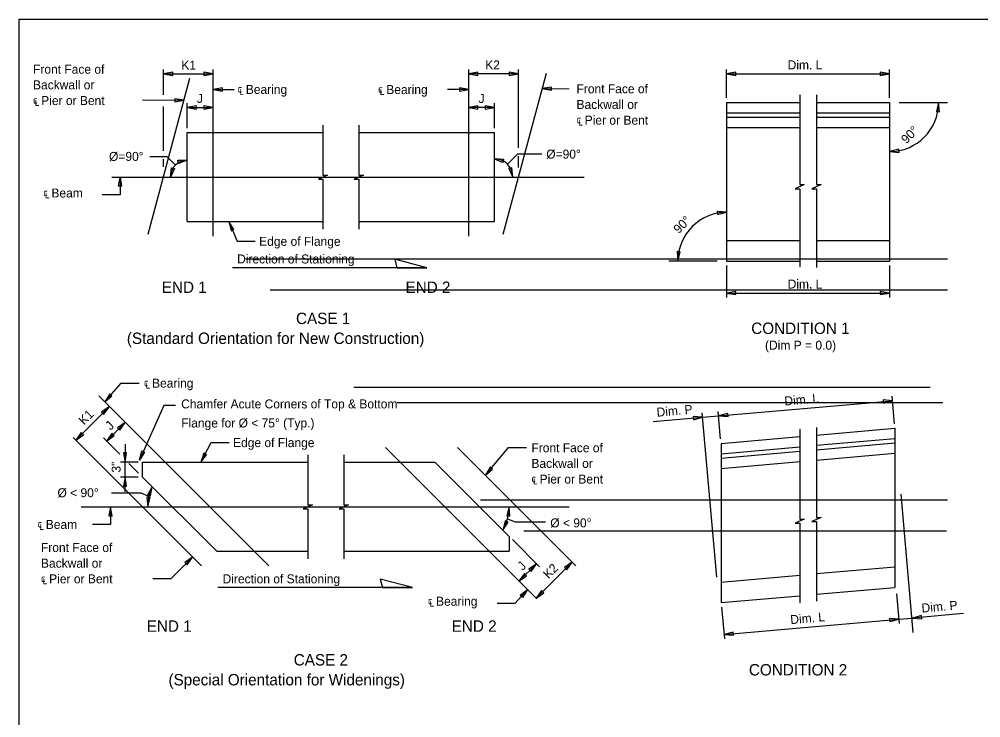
# Model space of a CAD drawing. Extents: x -119 to 80, y -12 to 144.
# Drawn here: x -12.03 to 4.16, y 47.86 to 59.63 of the extents above; entities that cross this region are included whole.
import ezdxf

# ---------------------------------------------------------------- set-up
doc = ezdxf.new("R2010")
doc.units = 0
for name, color, linetype in [('ActivePts-ConstElements', 7, 'Continuous'), ('AdhocPoint_dp', 7, 'Continuous'), ('CL_Major', 7, 'Continuous'), ('Patterning', 7, 'Continuous'), ('SheetLines_dp', 7, 'Continuous'), ('TextMisc', 7, 'Continuous')]:
    doc.layers.add(name, color=color, linetype=linetype)

msp = doc.modelspace()

# ---------------------------------------------------------------- linework, layer by layer
at = {"layer": 'ActivePts-ConstElements'}
msp.add_lwpolyline([(-12.032, 59.628), (18.768, 59.628), (18.768, 39.828), (-12.032, 39.828)], close=True, dxfattribs=at)
at = {"layer": 'AdhocPoint_dp'}
for p, q in [((-9.604, 58.355), (-9.604, 58.783)), ((-3.626, 57.46), (-3.626, 58.783)), ((-0.122, 58.302), (-0.122, 58.783)), ((2.623, 58.302), (2.623, 58.783)), ((-9.604, 58.707), (-8.766, 58.707)), ((-3.626, 58.707), (-4.464, 58.707)), ((-0.122, 58.707), (2.623, 58.707)), ((-3.227, 58.46), (-2.772, 58.457)), ((-8.766, 58.444), (-8.411, 58.444)), ((-4.464, 58.444), (-4.82, 58.444)), ((-9.258, 58.263), (-9.954, 58.259)), ((-9.604, 57.412), (-9.604, 58.157)), ((-9.202, 57.796), (-9.202, 58.217)), ((-9.202, 58.141), (-8.766, 58.141)), ((-4.029, 58.141), (-4.464, 58.141)), ((-4.029, 57.796), (-4.029, 58.217)), ((2.786, 58.226), (3.599, 58.226)), ((-3.626, 57.132), (-3.626, 57.322)), ((-9.604, 57.14), (-9.604, 57.27)), ((-10.334, 56.97), (-10.334, 56.669)), ((-10.334, 56.669), (-10.637, 56.669)), ((-8.501, 56.22), (-8.362, 55.888)), ((-8.362, 55.888), (-8.06, 55.888)), ((-0.28, 55.556), (-1.093, 55.556)), ((-5.167, 55.444), (-8.442, 55.444)), ((-0.122, 55.481), (-0.122, 54.942)), ((2.623, 55.481), (2.623, 54.942)), ((-0.122, 55.017), (2.623, 55.017)), ((-10.592, 53.183), (-10.315, 53.5)), ((-10.315, 53.5), (-10.012, 53.5)), ((2.706, 52.816), (2.665, 53.279)), ((-11.081, 52.538), (-10.514, 53.105)), ((-0.256, 52.948), (2.672, 53.204)), ((-0.289, 50.233), (-0.531, 53)), ((-0.525, 52.924), (-0.256, 52.948)), ((-0.222, 52.56), (-0.263, 53.023)), ((-10.561, 52.524), (-10.247, 52.838)), ((-1.356, 52.852), (-0.525, 52.924)), ((-10.338, 52.301), (-10.615, 52.577)), ((-10.249, 52.47), (-10.249, 52.168)), ((-8.975, 52.168), (-8.802, 52.498)), ((-8.802, 52.498), (-8.499, 52.498)), ((-4.184, 51.948), (-3.792, 52.415)), ((-3.792, 52.415), (-3.489, 52.415)), ((-10.031, 52.168), (-10.325, 52.168)), ((-10.249, 51.918), (-10.249, 52.168)), ((-10.023, 51.985), (-10.184, 52.147)), ((-10.031, 51.918), (-10.325, 51.918)), ((-10.249, 51.671), (-10.249, 51.918)), ((2.81, 51.63), (3.013, 49.302)), ((-10.495, 51.418), (-10.497, 51.119)), ((-10.497, 51.119), (-10.799, 51.119)), ((-3.729, 50.864), (-3.27, 50.405)), ((-9.113, 50.57), (-9.479, 50.203)), ((-3.323, 50.459), (-3.618, 50.165)), ((-3.33, 49.877), (-2.722, 50.485)), ((-9.479, 50.203), (-9.782, 50.203)), ((-5.411, 50.057), (-8.687, 50.057)), ((2.741, 49.951), (2.785, 49.449)), ((-0.206, 49.728), (-0.159, 49.191)), ((2.778, 49.524), (3.007, 49.544)), ((3.865, 49.619), (3.007, 49.544)), ((-0.165, 49.266), (2.778, 49.524))]:
    msp.add_line(p, q, dxfattribs=at)
for points in [[(-9.604, 58.707), (-9.448, 58.681), (-9.448, 58.734)], [(-8.766, 58.707), (-8.923, 58.734), (-8.923, 58.681)], [(-4.464, 58.707), (-4.308, 58.681), (-4.308, 58.734)], [(-3.626, 58.707), (-3.783, 58.734), (-3.783, 58.681)], [(-0.122, 58.707), (0.034, 58.681), (0.034, 58.734)], [(2.623, 58.707), (2.466, 58.734), (2.466, 58.681)], [(-8.766, 58.444), (-8.61, 58.417), (-8.61, 58.47)], [(-4.464, 58.444), (-4.621, 58.47), (-4.621, 58.417)], [(-3.227, 58.46), (-3.071, 58.432), (-3.071, 58.485)], [(-9.258, 58.263), (-9.414, 58.289), (-9.414, 58.236)], [(-9.202, 58.141), (-9.046, 58.115), (-9.046, 58.168)], [(-8.766, 58.141), (-8.923, 58.168), (-8.923, 58.115)], [(-4.464, 58.141), (-4.308, 58.115), (-4.308, 58.168)], [(-4.029, 58.141), (-4.185, 58.168), (-4.185, 58.115)], [(3.448, 58.226), (3.41, 58.072), (3.463, 58.068)], [(2.623, 57.398), (2.781, 57.385), (2.776, 57.438)], [(-9.202, 57.254), (-9.351, 57.2), (-9.36, 57.252)], [(-4.029, 57.277), (-3.883, 57.215), (-3.871, 57.266)], [(-9.486, 56.97), (-9.47, 57.128), (-9.419, 57.114)], [(-3.722, 56.97), (-3.737, 57.128), (-3.788, 57.115)], [(-10.334, 56.97), (-10.308, 56.814), (-10.361, 56.814)], [(-0.121, 56.379), (-0.279, 56.392), (-0.275, 56.339)], [(-8.501, 56.22), (-8.465, 56.066), (-8.416, 56.086)], [(-0.943, 55.557), (-0.901, 55.71), (-0.954, 55.715)], [(-0.122, 55.017), (0.034, 54.991), (0.034, 55.044)], [(2.623, 55.017), (2.466, 55.044), (2.466, 54.991)], [(-10.592, 53.183), (-10.47, 53.283), (-10.509, 53.318)], [(-10.514, 53.105), (-10.644, 53.013), (-10.606, 52.976)], [(2.672, 53.204), (2.514, 53.217), (2.519, 53.164)], [(-0.256, 52.948), (-0.098, 52.935), (-0.103, 52.988)], [(-10.247, 52.838), (-10.376, 52.746), (-10.339, 52.709)], [(-0.525, 52.924), (-0.682, 52.937), (-0.678, 52.884)], [(-11.081, 52.538), (-10.952, 52.63), (-10.989, 52.667)], [(-10.561, 52.524), (-10.432, 52.616), (-10.47, 52.653)], [(-10.249, 52.168), (-10.223, 52.324), (-10.276, 52.324)], [(-9.921, 52.335), (-10.008, 52.203), (-9.969, 52.357)], [(-8.975, 52.168), (-8.879, 52.294), (-8.926, 52.318)], [(-4.184, 51.948), (-4.063, 52.05), (-4.104, 52.084)], [(-10.249, 51.918), (-10.276, 51.762), (-10.223, 51.762)], [(-9.791, 51.754), (-9.873, 51.618), (-9.823, 51.599)], [(-9.868, 51.418), (-9.83, 51.571), (-9.883, 51.575)], [(-10.495, 51.418), (-10.522, 51.262), (-10.469, 51.261)], [(-3.784, 51.418), (-3.822, 51.264), (-3.769, 51.26)], [(-3.89, 51.026), (-3.801, 51.157), (-3.85, 51.179)], [(-9.113, 50.57), (-9.242, 50.478), (-9.205, 50.441)], [(-3.323, 50.459), (-3.453, 50.367), (-3.415, 50.33)], [(-2.722, 50.485), (-2.851, 50.393), (-2.813, 50.356)], [(-3.618, 50.165), (-3.489, 50.256), (-3.526, 50.294)], [(-3.599, 49.927), (-3.474, 50.025), (-3.56, 49.892)], [(-3.33, 49.877), (-3.201, 49.968), (-3.238, 50.006)], [(3.007, 49.544), (3.165, 49.531), (3.16, 49.584)], [(2.778, 49.524), (2.62, 49.537), (2.625, 49.484)], [(-0.165, 49.266), (-0.007, 49.254), (-0.012, 49.306)]]:
    msp.add_lwpolyline(points, close=True, dxfattribs=at)
for points in [[(1.109, 58.357), (1.109, 56.842), (1.186, 56.842), (1.031, 56.774), (1.109, 56.774), (1.109, 55.456)], [(1.391, 58.357), (1.391, 56.842), (1.469, 56.842), (1.314, 56.774), (1.391, 56.774), (1.391, 55.447)], [(-6.918, 57.845), (-6.918, 57.004), (-6.84, 57.004), (-6.995, 56.937), (-6.918, 56.937), (-6.918, 56.095)], [(-6.313, 57.845), (-6.313, 57.004), (-6.236, 57.004), (-6.391, 56.937), (-6.313, 56.937), (-6.313, 56.095)], [(-9.403, 57.171), (-9.543, 57.312), (-9.834, 57.312)], [(-3.812, 57.187), (-3.639, 57.36), (-3.231, 57.36)], [(-9.4, 53.124), (-9.599, 53.124), (-10.008, 52.203)], [(1.109, 52.726), (1.109, 51.21), (1.186, 51.21), (1.031, 51.143), (1.109, 51.143), (1.109, 49.801)], [(1.391, 52.75), (1.391, 51.235), (1.469, 51.235), (1.314, 51.167), (1.391, 51.167), (1.391, 49.828)], [(-7.171, 52.293), (-7.171, 51.451), (-7.094, 51.451), (-7.249, 51.384), (-7.171, 51.384), (-7.171, 50.543)], [(-6.566, 52.293), (-6.566, 51.451), (-6.489, 51.451), (-6.644, 51.384), (-6.566, 51.384), (-6.566, 50.543)], [(-9.848, 51.59), (-9.978, 51.644), (-10.476, 51.644)], [(-3.811, 51.215), (-3.681, 51.161), (-3.173, 51.161)], [(-3.987, 49.796), (-3.683, 49.796), (-3.474, 50.025)]]:
    msp.add_lwpolyline(points, dxfattribs=at)
for centre, radius, start, end in [((2.62, 58.226), 0.828, 270.1769, 0), ((-9.202, 56.97), 0.284, 90, 180), ((-4.029, 56.97), 0.307, 0, 90), ((-0.115, 55.551), 0.828, 90.45, 179.6009), ((-9.094, 51.418), 0.774, 154.2882, 180), ((-4.558, 51.418), 0.774, 329.5876, 360)]:
    msp.add_arc(centre, radius, start, end, dxfattribs=at)
at = {"layer": 'CL_Major'}
for p, q in [((-8.766, 55.974), (-8.766, 58.783)), ((-4.464, 55.974), (-4.464, 58.783)), ((-9.862, 56.008), (-9.158, 58.636)), ((-3.884, 56.008), (-3.157, 58.721)), ((-10.472, 56.97), (-2.522, 56.97)), ((-7.831, 50.422), (-10.692, 53.283)), ((-8.964, 50.422), (-11.124, 52.582)), ((-3.318, 49.865), (-5.867, 52.414)), ((-2.658, 50.422), (-4.65, 52.414)), ((-10.987, 51.418), (-2.775, 51.418))]:
    msp.add_line(p, q, dxfattribs=at)
at = {"layer": 'Patterning'}
for p, q in [((-0.122, 58.226), (-0.122, 55.556)), ((-0.122, 58.226), (1.109, 58.226)), ((1.391, 58.226), (2.623, 58.226)), ((2.623, 58.226), (2.623, 55.556)), ((-0.122, 58.053), (1.109, 58.053)), ((-0.122, 57.979), (1.109, 57.979)), ((1.391, 58.053), (2.623, 58.053)), ((1.391, 57.979), (2.623, 57.979)), ((-0.122, 57.806), (1.109, 57.806)), ((1.391, 57.806), (2.623, 57.806)), ((-9.202, 56.22), (-9.202, 57.72)), ((-9.202, 57.72), (-6.918, 57.72)), ((-6.313, 57.72), (-4.029, 57.72)), ((-4.029, 56.22), (-4.029, 57.72)), ((-9.202, 56.22), (-6.918, 56.22)), ((-6.313, 56.22), (-4.029, 56.22)), ((-0.122, 55.902), (1.109, 55.902)), ((1.391, 55.902), (2.623, 55.902)), ((-0.122, 55.556), (1.109, 55.556)), ((1.391, 55.556), (2.623, 55.556)), ((1.391, 52.625), (2.712, 52.741)), ((2.712, 52.741), (2.713, 50.059)), ((-0.212, 52.485), (1.109, 52.601)), ((-0.212, 52.485), (-0.212, 49.803)), ((1.391, 52.452), (2.712, 52.567)), ((1.391, 52.377), (2.712, 52.493)), ((-0.212, 52.311), (1.109, 52.427)), ((-0.212, 52.237), (1.109, 52.352)), ((1.391, 52.203), (2.712, 52.319)), ((-9.955, 51.918), (-9.955, 52.168)), ((-9.955, 52.168), (-7.171, 52.168)), ((-6.566, 52.168), (-5.032, 52.168)), ((-5.032, 52.168), (-3.782, 50.918)), ((-0.212, 52.063), (1.109, 52.179)), ((-8.705, 50.668), (-9.955, 51.918)), ((-3.782, 50.918), (-3.782, 50.668)), ((-8.705, 50.668), (-7.171, 50.668)), ((-6.566, 50.668), (-3.782, 50.668)), ((1.391, 50.291), (2.713, 50.406)), ((-0.212, 50.15), (1.109, 50.266)), ((1.391, 49.943), (2.713, 50.059)), ((-0.212, 49.803), (1.109, 49.918))]:
    msp.add_line(p, q, dxfattribs=at)
at = {"layer": 'SheetLines_dp'}
for p, q in [((-8.221, 55.59), (3.598, 55.59)), ((-7.805, 55.069), (3.598, 55.069)), ((3.308, 53.428), (-6.398, 53.428)), ((3.52, 53.168), (-5.669, 53.168)), ((3.598, 51.527), (-4.263, 51.527)), ((3.578, 51.006), (-3.534, 51.006))]:
    msp.add_line(p, q, dxfattribs=at)
at = {"layer": 'TextMisc'}
for points in [[(-5.709, 55.587), (-5.674, 55.444), (-5.167, 55.444)], [(-5.954, 50.2), (-5.918, 50.057), (-5.411, 50.057)]]:
    msp.add_lwpolyline(points, close=True, dxfattribs=at)

# ---------------------------------------------------------------- texts
for s, height, p in [('K2', 0.1512, (-4.186, 58.783)), ('Dim. L', 0.1512, (0.906, 58.783)), ('Front Face of', 0.1512, (-11.8, 58.71)), ('K1', 0.1512, (-9.302, 58.779)), ('Backwall or', 0.1512, (-11.8, 58.447)), ('℄ Bearing', 0.1512, (-8.355, 58.37)), ('℄ Bearing', 0.1512, (-5.99, 58.368)), ('Front Face of', 0.1512, (-2.649, 58.381)), ('℄ Pier or Bent', 0.1512, (-11.8, 58.183)), ('J', 0.151, (-9.041, 58.217)), ('J', 0.151, (-4.298, 58.217)), ('Backwall or', 0.1512, (-2.649, 58.117)), ('℄ Pier or Bent', 0.1512, (-2.649, 57.853)), ('Ø=90°', 0.1512, (-10.52, 57.242)), ('Ø=90°', 0.1512, (-3.158, 57.281)), ('℄ Beam', 0.1512, (-11.628, 56.626)), ('Edge of Flange', 0.1512, (-7.992, 55.812)), ('Direction of Stationing', 0.1512, (-8.364, 55.515)), ('END 1', 0.192, (-9.631, 55.019)), ('END 2', 0.192, (-5.528, 55.019)), ('Dim. L', 0.1512, (0.906, 55.093)), ('CASE 1', 0.192, (-7.372, 54.494)), ('CONDITION 1', 0.192, (0.293, 54.327)), ('(Standard Orientation for New Construction)', 0.192, (-10.22, 54.159)), ('(Dim P = 0.0)', 0.1512, (0.525, 54.063)), ('℄ Bearing', 0.1512, (-9.934, 53.424)), ('Chamfer Acute Corners of Top & Bottom ', 0.1512, (-9.305, 53.074)), ('Flange for Ø < 75° (Typ.)', 0.1512, (-9.305, 52.753)), ('Edge of Flange', 0.1512, (-8.432, 52.422)), ('Front Face of', 0.1512, (-3.408, 52.335)), ('Backwall or', 0.1512, (-3.408, 52.072)), ('℄ Pier or Bent', 0.1512, (-3.408, 51.808)), ('Ø < 90°', 0.1512, (-11.388, 51.578)), ('℄ Beam', 0.1512, (-11.723, 51.044)), ('Ø < 90°', 0.1512, (-3.091, 51.07)), ('Front Face of', 0.1512, (-11.666, 50.655)), ('Backwall or', 0.1512, (-11.666, 50.391)), ('℄ Pier or Bent', 0.1512, (-11.666, 50.128)), ('Direction of Stationing', 0.1512, (-8.608, 50.128)), ('℄ Bearing', 0.1512, (-5.152, 49.751)), ('END 1', 0.192, (-9.885, 49.312)), ('END 2', 0.192, (-4.75, 49.312)), ('CASE 2', 0.192, (-7.41, 48.744)), ('CONDITION 2', 0.192, (0.254, 48.576)), ('(Special Orientation for Widenings)', 0.192, (-9.519, 48.409))]:
    msp.add_text(s, height=height, dxfattribs=at).set_placement(p)
for s, height, rotation, p in [(' 90°', 0.1512, 45, (2.866, 57.481)), (' 90°', 0.1512, 45, (-0.968, 55.968)), ('Dim. L', 0.1512, 5.0005, (0.858, 53.121)), ('Dim. P', 0.1512, 5.0005, (-1.294, 52.933)), ('K1', 0.1512, 44.9945, (-10.941, 52.785)), ('J', 0.151, 44.9945, (-10.494, 52.698)), ('3"', 0.1512, 90, (-10.325, 51.993)), ('J', 0.151, 44.9945, (-3.554, 50.335)), ('K2', 0.1512, 44.9945, (-3.12, 50.194)), ('Dim. P', 0.1512, 5.0005, (3.167, 49.634)), ('Dim. L', 0.1512, 5.0005, (0.957, 49.44))]:
    msp.add_text(s, height=height, rotation=rotation, dxfattribs=at).set_placement(p)

doc.saveas('drawing.dxf')
